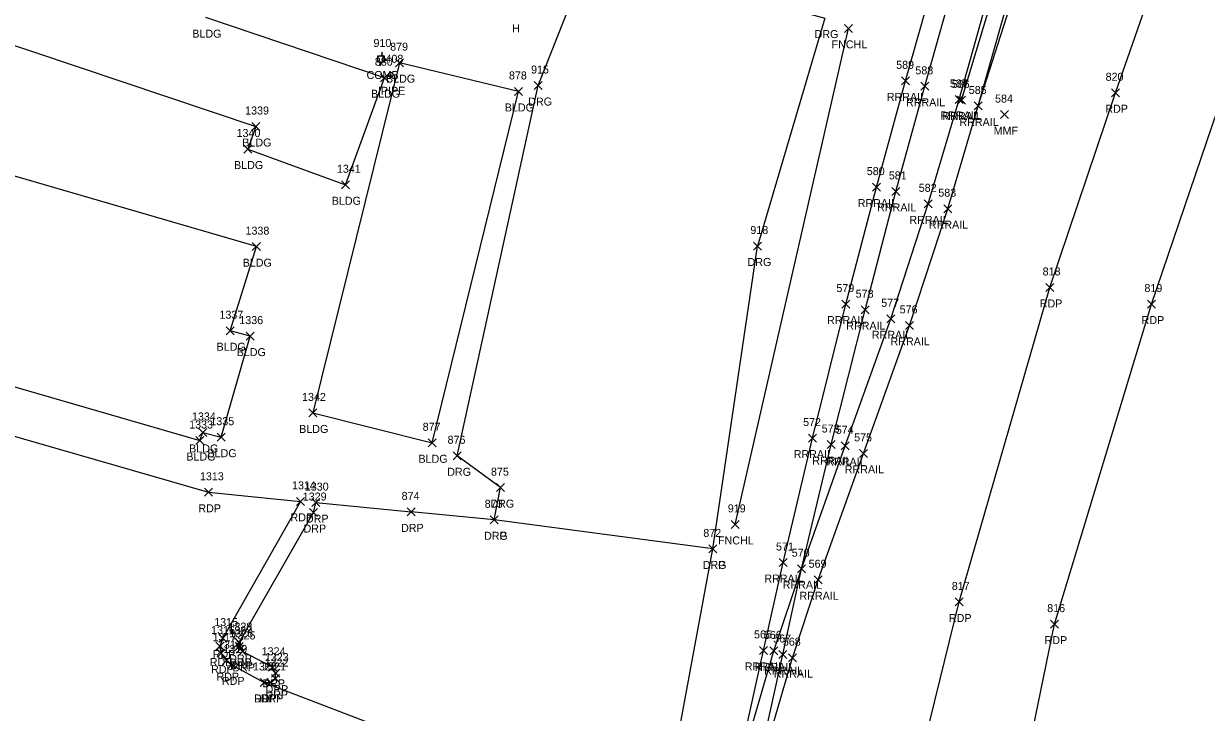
# Model space of a CAD drawing. Extents: x 1767353 to 1772625, y 740790 to 747702.
# Drawn here: x 1770037.2 to 1770332.7, y 741990.7 to 742162.8 of the extents above; entities that cross this region are included whole.
import ezdxf

# ---------------------------------------------------------------- set-up
doc = ezdxf.new("R2010")
doc.units = 0
for name, color, linetype in [('L_A', 7, 'Continuous'), ('L_I', 7, 'Continuous'), ('L_TIC', 7, 'Continuous'), ('LBC', 7, 'Continuous'), ('LFNC', 7, 'Continuous'), ('M_A', 7, 'Continuous'), ('M_I', 7, 'Continuous'), ('MPIP', 7, 'Continuous'), ('P_A', 7, 'Continuous'), ('P_I', 7, 'Continuous'), ('P_TIC', 7, 'Continuous'), ('PET', 7, 'Continuous'), ('R_A', 7, 'Continuous'), ('R_I', 7, 'Continuous'), ('R_TIC', 7, 'Continuous'), ('RDG', 7, 'Continuous'), ('RDP', 7, 'Continuous'), ('RR', 7, 'Continuous'), ('U_A', 7, 'Continuous'), ('U_I', 7, 'Continuous'), ('UP', 7, 'Continuous')]:
    doc.layers.add(name, color=color, linetype=linetype)

msp = doc.modelspace()

# ---------------------------------------------------------------- linework, layer by layer
at = {"layer": 'L_TIC'}
for points in [[(1770242.34, 742160.6), (1770244.34, 742162.6)], [(1770244.34, 742160.6), (1770242.34, 742162.6)], [(1770130.16, 742152.03), (1770132.16, 742154.03)], [(1770132.16, 742152.03), (1770130.16, 742154.03)], [(1770126.4, 742148.28), (1770128.4, 742150.28)], [(1770128.4, 742148.28), (1770126.4, 742150.28)], [(1770159.84, 742144.84), (1770161.84, 742146.84)], [(1770161.84, 742144.84), (1770159.84, 742146.84)], [(1770281.29, 742139.05), (1770283.29, 742141.05)], [(1770283.29, 742139.05), (1770281.29, 742141.05)], [(1770094.25, 742136.08), (1770096.25, 742138.08)], [(1770096.25, 742136.08), (1770094.25, 742138.08)], [(1770092.19, 742130.45), (1770094.19, 742132.45)], [(1770094.19, 742130.45), (1770092.19, 742132.45)], [(1770116.61, 742121.52), (1770118.61, 742123.52)], [(1770118.61, 742121.52), (1770116.61, 742123.52)], [(1770094.35, 742106.06), (1770096.35, 742108.06)], [(1770096.35, 742106.06), (1770094.35, 742108.06)], [(1770087.83, 742085.05), (1770089.83, 742087.05)], [(1770089.83, 742085.05), (1770087.83, 742087.05)], [(1770092.85, 742083.71), (1770094.85, 742085.71)], [(1770094.85, 742083.71), (1770092.85, 742085.71)], [(1770108.46, 742064.51), (1770110.46, 742066.51)], [(1770110.46, 742064.51), (1770108.46, 742066.51)], [(1770080.97, 742059.63), (1770082.97, 742061.63)], [(1770082.97, 742059.63), (1770080.97, 742061.63)], [(1770080.26, 742057.61), (1770082.26, 742059.61)], [(1770082.26, 742057.61), (1770080.26, 742059.61)], [(1770085.55, 742058.45), (1770087.55, 742060.45)], [(1770087.55, 742058.45), (1770085.55, 742060.45)], [(1770138.27, 742057.05), (1770140.27, 742059.05)], [(1770140.27, 742057.05), (1770138.27, 742059.05)], [(1770213.96, 742036.66), (1770215.96, 742038.66)], [(1770215.96, 742036.66), (1770213.96, 742038.66)]]:
    msp.add_lwpolyline(points, dxfattribs=at)
at = {"layer": 'LBC'}
for points in [[(1770013.44, 742188.44), (1770006.11, 742167), (1770095.25, 742137.08), (1770093.19, 742131.45), (1770117.61, 742122.52)], [(1769980.24, 742140.57), (1769986.99, 742164.16), (1769964.36, 742170.66), (1769967.04, 742179.73), (1769960.32, 742181.77), (1769957.53, 742172.47), (1769936.48, 742178.62), (1769915.07, 742106.78), (1770081.26, 742058.61), (1770081.97, 742060.63), (1770086.55, 742059.45), (1770093.85, 742084.71), (1770088.83, 742086.05), (1770095.35, 742107.06)], [(1770127.4, 742149.28), (1770082.76, 742164.28)], [(1770131.16, 742153.03), (1770109.46, 742065.51)], [(1770139.27, 742058.05), (1770160.84, 742145.84), (1770131.16, 742153.03)], [(1770117.61, 742122.52), (1770127.4, 742149.28)], [(1770095.35, 742107.06), (1769980.24, 742140.57)], [(1770109.46, 742065.51), (1770139.27, 742058.05)]]:
    msp.add_lwpolyline(points, dxfattribs=at)
at = {"layer": 'LFNC'}
msp.add_lwpolyline([(1770214.96, 742037.66), (1770243.34, 742161.6)], dxfattribs=at)
at = {"layer": 'MPIP'}
for radius in [0.625, 0.0833]:
    msp.add_circle((1770128.91, 742150), radius, dxfattribs=at)
at = {"layer": 'P_TIC'}
for points in [[(1770308.99, 742144.51), (1770310.99, 742146.51)], [(1770310.99, 742144.51), (1770308.99, 742146.51)], [(1770292.62, 742095.86), (1770294.62, 742097.86)], [(1770294.62, 742095.86), (1770292.62, 742097.86)], [(1770318.05, 742091.71), (1770320.05, 742093.71)], [(1770320.05, 742091.71), (1770318.05, 742093.71)], [(1770082.39, 742044.68), (1770084.39, 742046.68)], [(1770084.39, 742044.68), (1770082.39, 742046.68)], [(1770105.4, 742042.42), (1770107.4, 742044.42)], [(1770107.4, 742042.42), (1770105.4, 742044.42)], [(1770269.92, 742017.28), (1770271.92, 742019.28)], [(1770271.92, 742017.28), (1770269.92, 742019.28)], [(1770293.81, 742011.74), (1770295.81, 742013.74)], [(1770295.81, 742011.74), (1770293.81, 742013.74)], [(1770085.23, 742006.27), (1770087.23, 742008.27)], [(1770087.23, 742006.27), (1770085.23, 742008.27)], [(1770085.96, 742008.25), (1770087.96, 742010.25)], [(1770087.96, 742008.25), (1770085.96, 742010.25)], [(1770085.55, 742004.47), (1770087.55, 742006.47)], [(1770087.55, 742004.47), (1770085.55, 742006.47)], [(1770086.9, 742002.62), (1770088.9, 742004.62)], [(1770088.9, 742002.62), (1770086.9, 742004.62)], [(1770088.26, 742001.56), (1770090.26, 742003.56)], [(1770090.26, 742001.56), (1770088.26, 742003.56)], [(1770096.29, 741997.16), (1770098.29, 741999.16)], [(1770098.29, 741997.16), (1770096.29, 741999.16)]]:
    msp.add_lwpolyline(points, dxfattribs=at)
at = {"layer": 'PET'}
for points in [[(1770147.48, 742699.94), (1770126.77, 742647.43), (1770093.35, 742575.6), (1770087.72, 742564.06), (1770014.02, 742398.02), (1769942.32, 742243.2), (1769914.15, 742124.85), (1769908.32, 742119.68), (1769902.88, 742101.36), (1769903.35, 742099.19), (1769904.66, 742097.46), (1769909.68, 742095.79), (1770083.39, 742045.68), (1770106.4, 742043.42), (1770086.96, 742009.25), (1770086.23, 742007.27), (1770086.55, 742005.47), (1770087.9, 742003.62), (1770089.26, 742002.56), (1770097.29, 741998.16), (1770140.08, 741981.73)], [(1770243.74, 741939.41), (1770255.24, 741954.28), (1770270.92, 742018.28), (1770293.62, 742096.86), (1770309.99, 742145.51), (1770335.13, 742217.35), (1770370.55, 742306.75), (1770390.86, 742357.46), (1770403.22, 742384.01), (1770418.01, 742412.4), (1770432.62, 742430.87), (1770448.87, 742440.9), (1770468.46, 742446.31), (1770490.36, 742448.75), (1770521.27, 742448.09), (1770553.51, 742444.86)], [(1770285.65, 741912.36), (1770284.14, 741916.13), (1770280.49, 741942.89), (1770294.81, 742012.74), (1770319.05, 742092.71), (1770358.99, 742210.27), (1770391.26, 742298.45), (1770431.82, 742392.19)]]:
    msp.add_lwpolyline(points, dxfattribs=at)
at = {"layer": 'R_TIC'}
for points in [[(1770164.8, 742146.32), (1770166.8, 742148.32)], [(1770166.8, 742146.32), (1770164.8, 742148.32)], [(1770256.59, 742147.49), (1770258.59, 742149.49)], [(1770258.59, 742147.49), (1770256.59, 742149.49)], [(1770261.38, 742146.12), (1770263.38, 742148.12)], [(1770263.38, 742146.12), (1770261.38, 742148.12)], [(1770270, 742142.83), (1770272, 742144.83)], [(1770272, 742142.83), (1770270, 742144.83)], [(1770270.52, 742142.69), (1770272.52, 742144.69)], [(1770272.52, 742142.69), (1770270.52, 742144.69)], [(1770274.73, 742141.21), (1770276.73, 742143.21)], [(1770276.73, 742141.21), (1770274.73, 742143.21)], [(1770274.73, 742141.21), (1770276.73, 742143.21)], [(1770276.73, 742141.21), (1770274.73, 742143.21)], [(1770249.33, 742120.94), (1770251.33, 742122.94)], [(1770251.33, 742120.94), (1770249.33, 742122.94)], [(1770254.17, 742119.86), (1770256.17, 742121.86)], [(1770256.17, 742119.86), (1770254.17, 742121.86)], [(1770262.22, 742116.76), (1770264.22, 742118.76)], [(1770264.22, 742116.76), (1770262.22, 742118.76)], [(1770267.11, 742115.55), (1770269.11, 742117.55)], [(1770269.11, 742115.55), (1770267.11, 742117.55)], [(1770219.59, 742106.22), (1770221.59, 742108.22)], [(1770221.59, 742106.22), (1770219.59, 742108.22)], [(1770219.59, 742106.22), (1770221.59, 742108.22)], [(1770221.59, 742106.22), (1770219.59, 742108.22)], [(1770241.65, 742091.71), (1770243.65, 742093.71)], [(1770243.65, 742091.71), (1770241.65, 742093.71)], [(1770246.46, 742090.31), (1770248.46, 742092.31)], [(1770248.46, 742090.31), (1770246.46, 742092.31)], [(1770252.86, 742088.03), (1770254.86, 742090.03)], [(1770254.86, 742088.03), (1770252.86, 742090.03)], [(1770257.52, 742086.39), (1770259.52, 742088.39)], [(1770259.52, 742086.39), (1770257.52, 742088.39)], [(1770233.33, 742058.23), (1770235.33, 742060.23)], [(1770235.33, 742058.23), (1770233.33, 742060.23)], [(1770237.97, 742056.62), (1770239.97, 742058.62)], [(1770239.97, 742056.62), (1770237.97, 742058.62)], [(1770144.55, 742053.8), (1770146.55, 742055.8)], [(1770146.55, 742053.8), (1770144.55, 742055.8)], [(1770241.49, 742056.3), (1770243.49, 742058.3)], [(1770243.49, 742056.3), (1770241.49, 742058.3)], [(1770246.09, 742054.41), (1770248.09, 742056.41)], [(1770248.09, 742054.41), (1770246.09, 742056.41)], [(1770155.34, 742045.84), (1770157.34, 742047.84)], [(1770157.34, 742045.84), (1770155.34, 742047.84)], [(1770109.25, 742042.1), (1770111.25, 742044.1)], [(1770111.25, 742042.1), (1770109.25, 742044.1)], [(1770108.65, 742039.63), (1770110.65, 742041.63)], [(1770110.65, 742039.63), (1770108.65, 742041.63)], [(1770133.02, 742039.78), (1770135.02, 742041.78)], [(1770135.02, 742039.78), (1770133.02, 742041.78)], [(1770153.78, 742037.81), (1770155.78, 742039.81)], [(1770155.78, 742037.81), (1770153.78, 742039.81)], [(1770153.78, 742037.81), (1770155.78, 742039.81)], [(1770155.78, 742037.81), (1770153.78, 742039.81)], [(1770208.39, 742030.53), (1770210.39, 742032.53)], [(1770210.39, 742030.53), (1770208.39, 742032.53)], [(1770208.39, 742030.53), (1770210.39, 742032.53)], [(1770210.39, 742030.53), (1770208.39, 742032.53)], [(1770225.99, 742027.12), (1770227.99, 742029.12)], [(1770227.99, 742027.12), (1770225.99, 742029.12)], [(1770230.58, 742025.58), (1770232.58, 742027.58)], [(1770232.58, 742025.58), (1770230.58, 742027.58)], [(1770230.58, 742025.58), (1770232.58, 742027.58)], [(1770232.58, 742025.58), (1770230.58, 742027.58)], [(1770234.77, 742022.83), (1770236.77, 742024.83)], [(1770236.77, 742022.83), (1770234.77, 742024.83)], [(1770090.04, 742006.16), (1770092.04, 742008.16)], [(1770092.04, 742006.16), (1770090.04, 742008.16)], [(1770090.08, 742007.13), (1770092.08, 742009.13)], [(1770092.08, 742007.13), (1770090.08, 742009.13)], [(1770090.33, 742005.46), (1770092.33, 742007.46)], [(1770092.33, 742005.46), (1770090.33, 742007.46)], [(1770090.88, 742004.92), (1770092.88, 742006.92)], [(1770092.88, 742004.92), (1770090.88, 742006.92)], [(1770221.11, 742005.18), (1770223.11, 742007.18)], [(1770223.11, 742005.18), (1770221.11, 742007.18)], [(1770223.63, 742005.05), (1770225.63, 742007.05)], [(1770225.63, 742005.05), (1770223.63, 742007.05)], [(1770225.9, 742004.14), (1770227.9, 742006.14)], [(1770227.9, 742004.14), (1770225.9, 742006.14)], [(1770228.32, 742003.36), (1770230.32, 742005.36)], [(1770230.32, 742003.36), (1770228.32, 742005.36)], [(1770098.37, 742000.95), (1770100.37, 742002.95)], [(1770100.37, 742000.95), (1770098.37, 742002.95)], [(1770099.12, 741998.13), (1770101.12, 742000.13)], [(1770101.12, 741998.13), (1770099.12, 742000.13)], [(1770099.18, 741999.49), (1770101.18, 742001.49)], [(1770101.18, 741999.49), (1770099.18, 742001.49)], [(1770096.29, 741997.16), (1770098.29, 741999.16)], [(1770098.29, 741997.16), (1770096.29, 741999.16)], [(1770097.94, 741997.17), (1770099.94, 741999.17)], [(1770099.94, 741997.17), (1770097.94, 741999.17)]]:
    msp.add_lwpolyline(points, dxfattribs=at)
at = {"layer": 'RDG'}
for points in [[(1770154.78, 742038.81), (1770156.34, 742046.84), (1770145.55, 742054.8), (1770165.8, 742147.32), (1770178.77, 742180.23), (1770237.36, 742164.17), (1770220.59, 742107.22)], [(1770209.39, 742031.53), (1770220.59, 742107.22)]]:
    msp.add_lwpolyline(points, dxfattribs=at)
at = {"layer": 'RDP'}
for points in [[(1770097.29, 741998.16), (1770098.94, 741998.17), (1770100.12, 741999.13), (1770100.18, 742000.49), (1770099.37, 742001.95), (1770091.88, 742005.92), (1770091.33, 742006.46), (1770091.04, 742007.16), (1770091.08, 742008.13), (1770109.65, 742040.63), (1770110.25, 742043.1)], [(1770110.25, 742043.1), (1770134.02, 742040.78)], [(1770200.61, 741944.59), (1770195.01, 741953.62), (1770209.39, 742031.53), (1770154.78, 742038.81), (1770134.02, 742040.78)]]:
    msp.add_lwpolyline(points, dxfattribs=at)
at = {"layer": 'RR'}
for points in [[(1770221.78, 741982.04), (1770226.9, 742005.14), (1770231.58, 742026.58), (1770238.97, 742057.62), (1770247.46, 742091.31), (1770255.17, 742120.86), (1770262.38, 742147.12), (1770270.79, 742177.04), (1770278.58, 742203.25), (1770285.57, 742226.22), (1770292.18, 742247.12), (1770303.7, 742282.6), (1770315.3, 742316.87), (1770330.35, 742359.31), (1770344.25, 742396.26), (1770362.68, 742444.08), (1770381.25, 742488.48), (1770399.89, 742531.75), (1770427.72, 742593.02), (1770459.92, 742661.06), (1770775.2, 743314.07), (1770996.39, 743772.66), (1771192.02, 744177.67), (1771329.71, 744462.72)], [(1770217.88, 741982.89), (1770224.63, 742006.05), (1770231.58, 742026.58), (1770242.49, 742057.3), (1770253.86, 742089.03), (1770263.22, 742117.76), (1770271, 742143.83), (1770279.57, 742174.49), (1770286.79, 742199.43), (1770293.9, 742223.08), (1770300.84, 742244.95), (1770311.67, 742279.15), (1770323.34, 742314.32), (1770337.98, 742356.11), (1770351.9, 742393.8), (1770370.52, 742441.44), (1770388.76, 742485.07), (1770407.79, 742528.71), (1770435.51, 742589.24), (1770468.44, 742657.89), (1770783.17, 743309.95), (1771004.51, 743768.91), (1771200.35, 744174.24), (1771337.45, 744458.43)], [(1770217.02, 741983.21), (1770222.11, 742006.18), (1770226.99, 742028.12), (1770234.33, 742059.23), (1770242.65, 742092.71), (1770250.33, 742121.94), (1770257.59, 742148.49), (1770265.95, 742178.19), (1770273.77, 742204.67), (1770280.68, 742227.53), (1770287.46, 742248.27), (1770299.11, 742284.6), (1770310.51, 742317.94), (1770325.96, 742361.53), (1770339.5, 742397.74), (1770358.03, 742445.88), (1770376.8, 742490.97), (1770395.2, 742533.35), (1770423.54, 742595.68), (1770455.2, 742662.62), (1770770.92, 743316.68), (1770991.9, 743774.87)], [(1770222.72, 741981.76), (1770229.32, 742004.36), (1770235.77, 742023.83), (1770247.09, 742055.41), (1770258.52, 742087.39), (1770268.11, 742116.55), (1770275.73, 742142.21), (1770291.55, 742198.01), (1770296.52, 742214.73), (1770305.48, 742243.41), (1770316.35, 742277.3), (1770328.03, 742312.86), (1770342.4, 742354.07), (1770356.59, 742392.13), (1770375.3, 742439.98), (1770392.87, 742482.18), (1770412.29, 742526.82), (1770439.88, 742586.94), (1770472.88, 742655.84), (1770787.34, 743307.49), (1771008.99, 743766.96)], [(1770271.52, 742143.69), (1770280.69, 742174.18), (1770289.74, 742198.6), (1770296.52, 742214.73), (1770308.93, 742241.95), (1770324.06, 742274.04), (1770340.68, 742308.04), (1770360.15, 742345.64), (1770381.03, 742382.61), (1770407.02, 742424.16), (1770425.18, 742450.58), (1770450.26, 742483.52), (1770473.18, 742510.79), (1770518.15, 742562.81), (1770572.7, 742627.85), (1770598.36, 742661.22), (1770630.52, 742706.14), (1770655.11, 742743.9), (1770674.5, 742775.55), (1770683.79, 742791.45), (1770706.15, 742833.16), (1770731.07, 742883.64), (1770775.22, 742979.87)], [(1770275.73, 742142.21), (1770285.7, 742173.47), (1770294.36, 742196.77), (1770301.28, 742213.26), (1770313.54, 742240.29), (1770328.52, 742271.98), (1770345.02, 742305.68), (1770363.97, 742342.43), (1770385.56, 742380.58), (1770410.92, 742420.89), (1770428.56, 742446.86), (1770454.89, 742481.33), (1770476.7, 742507.31), (1770522.14, 742559.86), (1770576.25, 742624.32), (1770602.26, 742658.04), (1770634.11, 742702.9), (1770659.93, 742742.21), (1770678.83, 742773.23), (1770687.73, 742788.35), (1770710.35, 742830.29), (1770735.06, 742880.72), (1770779.65, 742978.02)]]:
    msp.add_lwpolyline(points, dxfattribs=at)
at = {"layer": 'UP'}
for p, q in [((1770125.67, 742153.12), (1770125.67, 742154.78)), ((1770125.67, 742154.78), (1770127.33, 742154.78)), ((1770127.33, 742153.12), (1770125.67, 742153.12)), ((1770126.25, 742152.28), (1770126.5, 742153.12)), ((1770126.75, 742155.62), (1770126.5, 742154.78)), ((1770126.5, 742153.95), (1770126.5, 742153.95)), ((1770127.33, 742154.78), (1770127.33, 742153.12))]:
    msp.add_line(p, q, dxfattribs=at)
msp.add_circle((1770126.5, 742153.95), 0.833, dxfattribs=at)

# ---------------------------------------------------------------- texts
at = {"layer": 'L_A'}
for s, p in [('H', (1770159.28, 742160.64)), ('BLDG', (1770079.35, 742159.28)), ('FNCHL', (1770239.08, 742156.6)), ('BLDG', (1770127.75, 742148.03)), ('BLDG', (1770123.99, 742144.28)), ('BLDG', (1770157.43, 742140.84)), ('MMF', (1770279.58, 742135.05)), ('BLDG', (1770091.84, 742132.08)), ('BLDG', (1770089.78, 742126.45)), ('BLDG', (1770114.2, 742117.52)), ('BLDG', (1770091.94, 742102.06)), ('BLDG', (1770085.42, 742081.05)), ('BLDG', (1770090.44, 742079.71)), ('BLDG', (1770106.05, 742060.51)), ('BLDG', (1770077.86, 742053.61)), ('BLDG', (1770078.56, 742055.63)), ('BLDG', (1770083.14, 742054.45)), ('BLDG', (1770135.86, 742053.05)), ('FNCHL', (1770210.7, 742032.66))]:
    msp.add_text(s, height=2, dxfattribs=at).set_placement(p)
at = {"layer": 'L_I'}
for s, p in [('879', (1770128.79, 742156.03)), ('880', (1770124.96, 742152.28)), ('878', (1770158.47, 742148.84)), ('584', (1770279.93, 742143.05)), ('1339', (1770092.55, 742140.08)), ('1340', (1770090.41, 742134.45)), ('1341', (1770115.48, 742125.52)), ('1338', (1770092.65, 742110.06)), ('1337', (1770086.14, 742089.05)), ('1336', (1770091.1, 742087.71)), ('1342', (1770106.77, 742068.51)), ('1334', (1770079.27, 742063.63)), ('1335', (1770083.86, 742062.45)), ('1333', (1770078.57, 742061.61)), ('877', (1770136.91, 742061.05)), ('919', (1770213.15, 742040.66))]:
    msp.add_text(s, height=2, dxfattribs=at).set_placement(p)
at = {"layer": 'M_A'}
msp.add_text('IPIPE', height=2, dxfattribs=at).set_placement((1770125.74, 742145))
at = {"layer": 'M_I'}
msp.add_text('1408', height=2, dxfattribs=at).set_placement((1770126.14, 742153))
at = {"layer": 'P_A'}
for p in [(1770307.48, 742140.51), (1770291.1, 742091.86), (1770316.54, 742087.71), (1770080.87, 742040.68), (1770103.89, 742038.42), (1770268.4, 742013.28), (1770292.3, 742007.74), (1770084.45, 742004.25), (1770083.72, 742002.27), (1770084.03, 742000.47), (1770085.39, 741998.62), (1770086.75, 741997.56), (1770094.78, 741993.16)]:
    msp.add_text('RDP', height=2, dxfattribs=at).set_placement(p)
at = {"layer": 'P_I'}
for s, p in [('820', (1770307.55, 742148.51)), ('818', (1770291.82, 742099.86)), ('819', (1770317.25, 742095.71)), ('1313', (1770081.26, 742048.68)), ('1314', (1770104.27, 742046.42)), ('817', (1770269.12, 742021.28)), ('816', (1770292.96, 742015.74)), ('1315', (1770084.83, 742012.25)), ('1316', (1770084.05, 742010.27)), ('1317', (1770084.42, 742008.47)), ('1318', (1770085.77, 742006.62)), ('1319', (1770087.13, 742005.56)), ('1320', (1770094.51, 742001.16))]:
    msp.add_text(s, height=2, dxfattribs=at).set_placement(p)
at = {"layer": 'R_A'}
for s, p in [('DRG', (1770234.84, 742159.17)), ('DRG', (1770163.29, 742142.32)), ('RRRAIL', (1770252.88, 742143.49)), ('RRRAIL', (1770257.67, 742142.12)), ('RRRAIL', (1770266.29, 742138.83)), ('RRRAIL', (1770266.81, 742138.69)), ('RRRAIL', (1770271.02, 742137.21)), ('RRRAIL', (1770271.02, 742137.21)), ('RRRAIL', (1770245.62, 742116.94)), ('RRRAIL', (1770250.47, 742115.86)), ('RRRAIL', (1770258.51, 742112.76)), ('RRRAIL', (1770263.4, 742111.55)), ('DRG', (1770218.08, 742102.22)), ('DRG', (1770218.08, 742102.22)), ('RRRAIL', (1770237.94, 742087.71)), ('RRRAIL', (1770242.75, 742086.31)), ('RRRAIL', (1770249.15, 742084.03)), ('RRRAIL', (1770253.81, 742082.39)), ('RRRAIL', (1770229.62, 742054.23)), ('RRRAIL', (1770234.26, 742052.62)), ('RRRAIL', (1770237.78, 742052.3)), ('DRG', (1770143.04, 742049.8)), ('RRRAIL', (1770242.38, 742050.41)), ('DRG', (1770153.83, 742041.84)), ('DRP', (1770107.74, 742038.1)), ('DRP', (1770131.51, 742035.78)), ('DRP', (1770107.14, 742035.63)), ('DRG', (1770152.26, 742033.81)), ('DRP', (1770152.26, 742033.81)), ('DRG', (1770206.88, 742026.53)), ('DRP', (1770206.88, 742026.53)), ('RRRAIL', (1770222.28, 742023.12)), ('RRRAIL', (1770226.87, 742021.58)), ('RRRAIL', (1770226.87, 742021.58)), ('RRRAIL', (1770231.06, 742018.83)), ('DRP', (1770088.53, 742002.16)), ('DRP', (1770088.57, 742003.13)), ('DRP', (1770088.82, 742001.46)), ('DRP', (1770089.36, 742000.92)), ('RRRAIL', (1770217.4, 742001.18)), ('RRRAIL', (1770219.92, 742001.05)), ('RRRAIL', (1770222.19, 742000.14)), ('RRRAIL', (1770224.61, 741999.36)), ('DRP', (1770096.86, 741996.95)), ('DRP', (1770097.67, 741995.49)), ('DRP', (1770094.78, 741993.16)), ('DRP', (1770096.43, 741993.17)), ('DRP', (1770097.61, 741994.13))]:
    msp.add_text(s, height=2, dxfattribs=at).set_placement(p)
at = {"layer": 'R_I'}
for s, p in [('589', (1770255.22, 742151.49)), ('915', (1770164, 742150.32)), ('588', (1770260.02, 742150.12)), ('587', (1770268.64, 742146.83)), ('586', (1770269.1, 742146.69)), ('585', (1770273.36, 742145.21)), ('585', (1770273.36, 742145.21)), ('580', (1770247.88, 742124.94)), ('581', (1770253.38, 742123.86)), ('582', (1770260.86, 742120.76)), ('583', (1770265.75, 742119.55)), ('918', (1770218.79, 742110.22)), ('918', (1770218.79, 742110.22)), ('579', (1770240.28, 742095.71)), ('578', (1770245.1, 742094.31)), ('577', (1770251.49, 742092.03)), ('576', (1770256.1, 742090.39)), ('572', (1770231.97, 742062.23)), ('573', (1770236.61, 742060.62)), ('574', (1770240.13, 742060.3)), ('876', (1770143.13, 742057.8)), ('575', (1770244.72, 742058.41)), ('875', (1770153.98, 742049.84)), ('1330', (1770107.47, 742046.1)), ('1329', (1770106.95, 742043.63)), ('874', (1770131.66, 742043.78)), ('873', (1770152.41, 742041.81)), ('873', (1770152.41, 742041.81)), ('872', (1770207.03, 742034.53)), ('872', (1770207.03, 742034.53)), ('571', (1770225.2, 742031.12)), ('570', (1770229.13, 742029.58)), ('570', (1770229.13, 742029.58)), ('569', (1770233.35, 742026.83)), ('1327', (1770088.35, 742010.16)), ('1328', (1770088.39, 742011.13)), ('1326', (1770088.58, 742009.46)), ('565', (1770219.7, 742009.18)), ('1325', (1770089.18, 742008.92)), ('566', (1770222.16, 742009.05)), ('567', (1770224.49, 742008.14)), ('568', (1770226.91, 742007.36)), ('1324', (1770096.68, 742004.95)), ('1323', (1770097.49, 742003.49)), ('1320', (1770094.51, 742001.16)), ('1321', (1770096.81, 742001.17)), ('1322', (1770097.42, 742002.13))]:
    msp.add_text(s, height=2, dxfattribs=at).set_placement(p)
at = {"layer": 'U_A'}
msp.add_text('COMB', height=2, dxfattribs=at).set_placement((1770122.89, 742148.95))
at = {"layer": 'U_I'}
msp.add_text('910', height=2, dxfattribs=at).set_placement((1770124.62, 742156.95))

doc.saveas('drawing.dxf')
